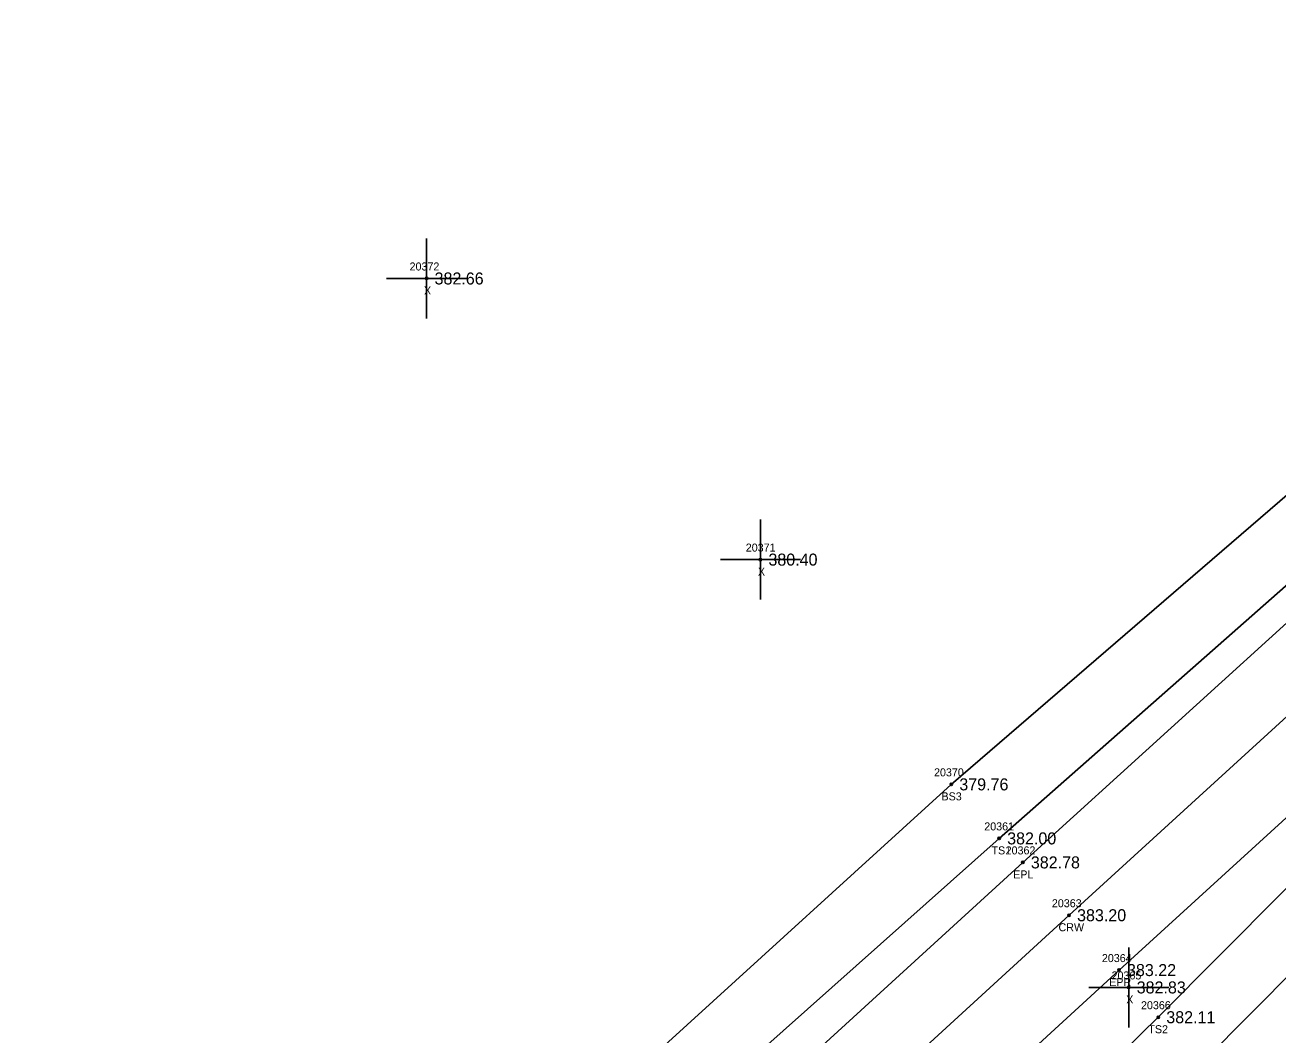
# Model space of a CAD drawing. Extents: x 2116373 to 2118139, y 979529 to 981026.
# Drawn here: x 2117493 to 2117649.6, y 980379.2 to 980505.4 of the extents above; entities that cross this region are included whole.
import ezdxf

# ---------------------------------------------------------------- set-up
doc = ezdxf.new("R2010")
doc.units = 0
for name, color, linetype in [('RD_DTM_BkLn1', 7, 'Continuous'), ('RD_DTM_BkLn2', 7, 'Continuous'), ('RD_DTM_BkLn_txCode', 7, 'Continuous'), ('RD_EX_Misc', 7, 'Continuous'), ('RD_EX_Misc_txCode', 7, 'Continuous'), ('RD_EX_Road', 7, 'Continuous'), ('RD_EX_Road_txCode', 7, 'Continuous'), ('RD_EX_TX_Misc_ELEV', 7, 'Continuous'), ('RD_EX_TX_Road_ELEV', 7, 'Continuous'), ('RD_HC_Survey_ELEV', 7, 'Continuous'), ('RD_HC_Survey_txCode', 7, 'Continuous'), ('RD_SMD_Locator', 7, 'Continuous')]:
    doc.layers.add(name, color=color, linetype=linetype)

msp = doc.modelspace()

# ---------------------------------------------------------------- linework, layer by layer
at = {"layer": 'RD_DTM_BkLn1'}
msp.add_lwpolyline([(2117394.63, 980185.41), (2117475.35, 980259.39), (2117549.63, 980326.58), (2117623.5, 980394.2), (2117697.55, 980461.75), (2117735.02, 980495.39), (2117805.43, 980566.78), (2117837.53, 980605.36), (2117867.93, 980645.06), (2117897.09, 980686.34), (2117923.66, 980727.51), (2117948.72, 980771.39), (2117971.22, 980818.34), (2117988.96, 980866.05), (2117991.42, 980873.14), (2118004.26, 980915.09), (2118016.82, 980963.49), (2118028.02, 981013.26)], dxfattribs=at)
at = {"layer": 'RD_DTM_BkLn2'}
for points in [[(2117493.39, 980317.39), (2117496.3, 980311.64), (2117501.39, 980308.35), (2117540.21, 980337.44), (2117614.76, 980403.8), (2117689.51, 980469.61), (2117729.91, 980504.53), (2117761.86, 980538.86), (2117795.32, 980575.41), (2117828.25, 980612.61), (2117859.59, 980651.69), (2117887.1, 980692.35), (2117913.78, 980733.2), (2117937.24, 980777.08), (2117959.23, 980820.82), (2117978.84, 980869.89), (2117994.26, 980920.18), (2118007.51, 980964.57), (2118017.18, 981016.23)], [(2117403.18, 980177.15), (2117405.35, 980174.66), (2117487.26, 980245.43), (2117563.99, 980312.17), (2117634.65, 980381.46), (2117704.3, 980451.46), (2117722.65, 980465.11), (2117743.87, 980484.9), (2117780.03, 980521.07), (2117815.83, 980557.8), (2117846.79, 980597.78), (2117878.62, 980636.27), (2117911.26, 980677.34), (2117934.7, 980720.41), (2117959.82, 980759.29), (2117971.51, 980778.31), (2117986.8, 980774.26), (2117987.85, 980770.9), (2117995.22, 980745.17), (2118001.26, 980694.98), (2118008.4, 980640.04)], [(2117537.18, 980345.39), (2117608.78, 980410.55), (2117660.7, 980455.28)], [(2117389.45, 980162.29), (2117496.47, 980234.47), (2117570.67, 980306.14), (2117640.42, 980376.1), (2117709.81, 980445.93), (2117716.62, 980450.81)]]:
    msp.add_lwpolyline(points, dxfattribs=at)
at = {"layer": 'RD_EX_Misc'}
for p, q in [((2117543.19, 980468.75), (2117543.19, 980478.75)), ((2117538.19, 980473.75), (2117548.19, 980473.75)), ((2117584.92, 980433.63), (2117584.92, 980443.63)), ((2117579.92, 980438.63), (2117589.92, 980438.63)), ((2117630.95, 980380.18), (2117630.95, 980390.18)), ((2117625.95, 980385.18), (2117635.95, 980385.18))]:
    msp.add_line(p, q, dxfattribs=at)
at = {"layer": 'RD_EX_Road'}
for points in [[(2117394.63, 980185.41), (2117388.45, 980192.75), (2117469.76, 980266.25), (2117487.02, 980282.1), (2117515.02, 980307.24), (2117543.53, 980333.04), (2117617.72, 980400.8), (2117691.88, 980468.07), (2117729.57, 980501.96), (2117798.93, 980572.83), (2117831.02, 980611), (2117861.69, 980650.07), (2117890.37, 980690.61), (2117916.67, 980731.93), (2117941.38, 980774.84), (2117963.75, 980821.95), (2117981.56, 980869.78), (2117996.2, 980917.73), (2118008.9, 980966.42), (2118019.55, 981015.46)], [(2117394.63, 980185.41), (2117401.85, 980177.36), (2117480.62, 980253.04), (2117556.27, 980319.95), (2117629.74, 980387.35), (2117703.2, 980454.29), (2117741.39, 980488.9), (2117777.53, 980523.58), (2117812.39, 980561.12), (2117844.66, 980599.64), (2117874.87, 980639.35), (2117904.78, 980681.4), (2117931.2, 980722.71), (2117957.05, 980767.35), (2117963.67, 980781.11), (2117980.28, 980814.62), (2117994.42, 980851.98)]]:
    msp.add_lwpolyline(points, dxfattribs=at)
at = {"layer": 'RD_SMD_Locator'}
for centre in [(2117543.19, 980473.75), (2117584.92, 980438.63), (2117608.78, 980410.55), (2117614.76, 980403.8), (2117617.72, 980400.8), (2117623.5, 980394.2), (2117629.74, 980387.35), (2117630.95, 980385.18), (2117634.65, 980381.46)]:
    msp.add_circle(centre, 0.15, dxfattribs=at)

# ---------------------------------------------------------------- texts
at = {"layer": 'RD_DTM_BkLn_txCode'}
for s, p in [('20370', (2117606.62, 980411.55)), ('BS3', (2117607.55, 980408.55)), ('20361', (2117612.9, 980404.8)), ('TS1', (2117613.8, 980401.8)), ('20366', (2117632.49, 980382.46)), ('TS2', (2117633.41, 980379.46))]:
    msp.add_text(s, height=1, dxfattribs=at).set_placement(p)
at = {"layer": 'RD_EX_Misc_txCode'}
for s, p in [('20372', (2117541.07, 980474.75)), ('X', (2117542.87, 980471.75)), ('20371', (2117583.09, 980439.63)), ('X', (2117584.61, 980436.63)), ('20365', (2117628.81, 980386.18)), ('X', (2117630.64, 980383.18))]:
    msp.add_text(s, height=1, dxfattribs=at).set_placement(p)
at = {"layer": 'RD_EX_Road_txCode'}
for s, p in [('20362', (2117615.57, 980401.8)), ('EPL', (2117616.51, 980398.8)), ('20364', (2117627.6, 980388.35)), ('EPR', (2117628.51, 980385.35))]:
    msp.add_text(s, height=1, dxfattribs=at).set_placement(p)
at = {"layer": 'RD_EX_TX_Misc_ELEV'}
for s, p in [('382.66', (2117544.19, 980473)), ('380.40', (2117585.92, 980437.88)), ('379.76', (2117609.78, 980409.8)), ('382.00', (2117615.76, 980403.05)), ('382.83', (2117631.95, 980384.43)), ('382.11', (2117635.65, 980380.71))]:
    msp.add_text(s, height=1.5, dxfattribs=at).set_placement(p)
at = {"layer": 'RD_EX_TX_Road_ELEV'}
for s, p in [('382.78', (2117618.72, 980400.05)), ('383.22', (2117630.74, 980386.6))]:
    msp.add_text(s, height=1.5, dxfattribs=at).set_placement(p)
at = {"layer": 'RD_HC_Survey_ELEV'}
msp.add_text('383.20', height=1.5, dxfattribs=at).set_placement((2117624.5, 980393.45))
at = {"layer": 'RD_HC_Survey_txCode'}
for s, p in [('20363', (2117621.35, 980395.2)), ('CRW', (2117622.18, 980392.2))]:
    msp.add_text(s, height=1, dxfattribs=at).set_placement(p)

doc.saveas('drawing.dxf')
